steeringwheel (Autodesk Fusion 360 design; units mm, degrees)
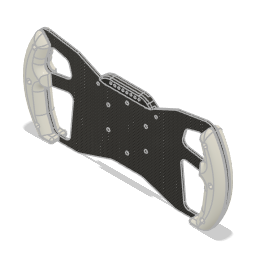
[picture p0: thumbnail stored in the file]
base_mesh_feature "Base Mesh Feature1"
base_mesh_feature "Base Mesh Feature2"
sketch "Sketch1" plane through (0, 0, 0) normal (0, 0, 1) x axis (1, 0, 0)
  line L1 (0, 45.0119) -> (-36.4037, 45.0119)
  line L2 (0, -55.8322) -> (-23.9037, -55.8322)
  line L3 (-78.4037, -74.0428) -> (-135.2692, -74.0428)
  line L4 (-78.4037, -74.0428) -> (-23.9037, -55.8322)
  line L5 (-36.4037, 45.0119) -> (-80, 65)
  line L6 (-80, 65) -> (-130.4747, 80.2858)
  line L7 (0, -94.3953) -> (0, 64.7225)
  line L8 (-162, -94.9093) -> (-162, 34.6125)
  line L9 (-87.3968, 22.1611) -> (-94.5571, 46.7526)
  line L10 (-133.0987, 14.2514) -> (-87.3968, 22.1611)
  line L11 (-129.3037, 34.2572) -> (-133.0987, 14.2514)
  line L12 (-122.9012, 54.3594) -> (-129.3037, 34.2572)
  line L13 (-94.5571, 46.7526) -> (-122.9012, 54.3594)
  line L14 (-85.8742, 4.1597) -> (-132.1872, -3.9752)
  line L15 (-92.2344, -65.3438) -> (-85.8742, 4.1597)
  line L16 (-117.9107, -65.3438) -> (-92.2344, -65.3438)
  line L17 (-127.1032, -41.9612) -> (-117.9107, -65.3438)
  line L18 (-132.1872, -3.9752) -> (-127.1032, -41.9612)
  line L19 (0, -55.8322) -> (0, 45.0119)
  line L20 (-137.7533, 71.7066) -> (-122.9012, 54.3594)
  line L21 (-135.2692, -74.0428) -> (-117.9107, -65.3438)
  line L22 (-121.746, -2.1412) -> (-123.3157, 15.9445)
  line L23 (-133.3138, 50.7008) -> (-134.7148, 46.7871)
  line L24 (-136.0027, 53.871) -> (-133.3138, 50.7008)
  line L25 (-140.0926, 53.1274) -> (-136.0027, 53.871)
  line L26 (-141.4936, 49.2136) -> (-140.0926, 53.1274)
  line L27 (-138.8046, 46.0435) -> (-141.4936, 49.2136)
  line L28 (-134.7148, 46.7871) -> (-138.8046, 46.0435)
  line L29 (-129.2785, -57.5552) -> (-131.7848, -60.8715)
  line L30 (-130.8973, -53.7264) -> (-129.2785, -57.5552)
  line L31 (-135.0226, -53.214) -> (-130.8973, -53.7264)
  line L32 (-137.5289, -56.5304) -> (-135.0226, -53.214)
  line L33 (-135.91, -60.3591) -> (-137.5289, -56.5304)
  line L34 (-131.7848, -60.8715) -> (-135.91, -60.3591)
  line L35 (-143.0554, 0.1029) -> (-142.9773, -4.0533)
  line L36 (-146.6938, 2.1134) -> (-143.0554, 0.1029)
  line L37 (-150.2541, -0.0323) -> (-146.6938, 2.1134)
  line L38 (-150.176, -4.1885) -> (-150.2541, -0.0323)
  line L39 (-146.5376, -6.199) -> (-150.176, -4.1885)
  line L40 (-142.9773, -4.0533) -> (-146.5376, -6.199)
  line L41 (-110.0525, -74.0428) -> (-110.0525, -65.3438)
  line L42 (-140.0719, -67.8017) -> (-120.4577, -58.8651)
  line L43 (-80, 65) -> (-135.8386, 74.1301)
  circle C1 centre (0, 35.0082) radius 2.5
  circle C2 centre (30.215, 17.6651) radius 2.5
  circle C3 centre (-30.371, 17.3955) radius 2.5
  circle C4 centre (-30.3591, -17.4163) radius 2.5
  circle C5 centre (0, -34.9879) radius 2.5
  circle C6 centre (30.2515, -17.6025) radius 2.5
  arc A1 centre (-45, 0.3916) radius 117 clockwise from (-135.2692, -74.0428) to (-130.4747, 80.2858)
  circle C7 centre (0, 0) radius 35
  circle C8 centre (-133.4037, -57.0428) radius 2.1
  circle C9 centre (-146.6157, -2.0428) radius 2.1
  circle C10 centre (-137.4037, 49.9572) radius 2.1
  circle C11 centre (-146.6157, -2.0428) radius 3.75
  circle C12 centre (-137.4037, 49.9572) radius 3.75
  circle C13 centre (-133.4037, -57.0428) radius 3.75
  point P6 (0, -34.9879)
  point P9 (0, 45.0119)
  point P11 (0, -55.8322)
  point P25 (-122.9012, 54.3594)
  point P23 (-133.0987, 14.2514)
  point P26 (-85.8742, 4.1597)
  point P2 (0, 35.0082)
  point P31 (0, 0)
  point P3 (30.215, 17.6651)
  point P7 (30.2515, -17.6025)
  point P5 (-30.3591, -17.4163)
  point P4 (-30.371, 17.3955)
  point P32 (-137.7533, 71.7066)
  point P33 (-123.3157, 15.9445)
  point P34 (-121.746, -2.1412)
  point P36 (-146.6157, -2.0428)
  point P38 (-146.6157, -2.0428)
  point P37 (-137.4037, 49.9572)
  point P45 (-137.4037, 49.9572)
  point P35 (-133.4037, -57.0428)
  point P52 (-133.4037, -57.0428)
  point P59 (-146.6157, -2.0428)
  point P60 (-146.6157, -2.0428)
  point P61 (-137.4037, 49.9572)
  point P62 (-133.4037, -57.0428)
  point P63 (-110.0525, -65.3438)
  point P64 (-110.0525, -74.0428)
  point P65 (-120.4577, -58.8651)
  point P66 (-140.0719, -67.8017)
  point P1 (0, 0)
  point P67 (-135.8386, 74.1301)
  horizontal L1
  parallel L1 L2
  horizontal L3
  perpendicular L2 L7
  coincident P6 L7
  coincident P9 L7
  coincident P11 L7
  vertical L8
  tangent A1 L8
  coincident P25 L13
  coincident L10 P23
  horizontal L16
  coincident L14 P26
  coincident P2 L7
  coincident L19 P31
  coincident P3 C7
  coincident P7 C7
  coincident P5 C7
  coincident P4 C7
  coincident A1 P32
  coincident L10 P33
  coincident L14 P34
  coincident P36 P38
  coincident P37 P45
  coincident P35 P52
  coincident P38 P59
  coincident P59 P60
  coincident P45 P61
  coincident P52 P62
  coincident L16 P63
  perpendicular L16 L41
  coincident L3 P64
  coincident L17 P65
  coincident A1 P66
  coincident P1 P31
  coincident A1 P67
  dimension "d1" diameter C1 = 5
  dimension "d2" diameter C2 = 5 (= "d1")
  dimension "d3" diameter C6 = 5 (= "d1")
  dimension "d4" diameter C5 = 5 (= "d1")
  dimension "d5" diameter C4 = 5 (= "d1")
  dimension "d6" diameter C3 = 5 (= "d1")
  dimension "d7" radius A1 = 117
  dimension "d9" distance L7 L8 = 162
  dimension "d21" diameter C7 = 70
  dimension "d37" diameter C8 = 4.2 (= "d39")
  dimension "d38" diameter C9 = 4.2 (= "d39")
  dimension "d39" diameter C10 = 4.2
  dimension "d41" distance P45 L28 = 3.6
  dimension "d42" distance P52 L34 = 3.6 (= "d41")
  dimension "d43" distance P59 L40 = 3.6 (= "d41")
  dimension "d44" diameter C11 = 7.5 (= "d45")
  dimension "d45" diameter C12 = 7.5
  dimension "d46" diameter C13 = 7.5 (= "d45")
extrude "Extrude1" new body sketch "Sketch1" profile of C1 C3 C4 C5 L1 L2 L3 L4 L5 A1 L9 L10 L11 L12 L13 L14 L15 L16 L17 L18 L19 C7 L20 L21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 along normal blind 3 bodies "BasePlate"
fillet "Fillet1" radius 8
fillet "Fillet2" radius 20
fillet "Fillet3" radius 8
modify "Modify2"
extrude "Extrude2" new body sketch "Sketch1" profile of A1 L10 L11 L12 L14 L17 L18 L20 L21 L22 along normal blind 15 and along normal blind 3 bodies "FrontGrip1"
extrude "Extrude3" new body sketch "Sketch1" profile of A1 L10 L11 L12 L14 L17 L18 L20 L21 L22 against normal blind 12 bodies "RearGrip1"
fillet "Fillet5" radius 8
fillet "Fillet6" radius 5
chamfer "Chamfer1" distance 7
fillet "Fillet7" radius 10
extrude "Extrude4" cut sketch "Sketch1" profile of C8 C9 C10 L23 L24 L25 L26 L27 L28 L29 L30 L31 L32 L33 L34 L35 L36 L37 L38 L39 L40 C11 C12 C13 along normal blind 25 and along normal blind 9
extrude "Extrude5" cut sketch "Sketch1" profile of C8 C9 C10 L37 along normal blind 25
extrude "Extrude6" cut sketch "Sketch1" profile of C8 C9 C10 C11 C12 C13 against normal blind 30 and against normal blind 6
extrude "Extrude7" cut sketch "Sketch1" profile of C8 C9 C10 L37 against normal blind 22
extrude "Extrude8" add sketch "Sketch1" profile of L3 A1 L16 L17 L21 L41 L42 against normal blind 12
extrude "Extrude9" add sketch "Sketch1" profile of L3 A1 L16 L17 L21 L41 L42 along normal blind 15 and along normal blind 3
fillet "Fillet9" radius 3
fillet "Fillet10" radius 10
fillet "Fillet11" radius 4
mirror "Mirror1" mirrorStitchTolerance 0.1
mirror "Mirror2" mirrorStitchTolerance 0.1 bodies "FrontGrip1 (1)", "RearGrip1 (1)"
fillet "Fillet12" radius 16
sketch "Sketch2" plane through (0, 0, 0) normal (0, 0, 1) x axis (1, 0, 0)
  line L1 (26.75, 57.2119) -> (-26.75, 57.2119)
  line L2 (26.75, 47.0119) -> (26.75, 57.2119)
  line L3 (-26.75, 47.0119) -> (26.75, 47.0119)
  line L4 (-26.75, 57.2119) -> (-26.75, 47.0119)
  line L5 (0, -49.4794) -> (0, 57.2119)
  line L6 (-20.25, 55.9119) -> (-25.75, 55.9119)
  line L7 (-20.25, 50.4119) -> (-20.25, 55.9119)
  line L8 (-25.75, 50.4119) -> (-20.25, 50.4119)
  line L9 (-25.75, 55.9119) -> (-25.75, 50.4119)
  line L10 (-13.75, 55.9119) -> (-19.25, 55.9119)
  line L11 (-13.75, 50.4119) -> (-13.75, 55.9119)
  line L12 (-19.25, 50.4119) -> (-13.75, 50.4119)
  line L13 (-19.25, 55.9119) -> (-19.25, 50.4119)
  line L14 (-7.25, 55.9119) -> (-12.75, 55.9119)
  line L15 (-7.25, 50.4119) -> (-7.25, 55.9119)
  line L16 (-12.75, 50.4119) -> (-7.25, 50.4119)
  line L17 (-12.75, 55.9119) -> (-12.75, 50.4119)
  line L18 (-0.75, 55.9119) -> (-6.25, 55.9119)
  line L19 (-0.75, 50.4119) -> (-0.75, 55.9119)
  line L20 (-6.25, 50.4119) -> (-0.75, 50.4119)
  line L21 (-6.25, 55.9119) -> (-6.25, 50.4119)
  line L22 (5.75, 55.9119) -> (0.25, 55.9119)
  line L23 (5.75, 50.4119) -> (5.75, 55.9119)
  line L24 (0.25, 50.4119) -> (5.75, 50.4119)
  line L25 (0.25, 55.9119) -> (0.25, 50.4119)
  line L26 (12.25, 55.9119) -> (6.75, 55.9119)
  line L27 (12.25, 50.4119) -> (12.25, 55.9119)
  line L28 (6.75, 50.4119) -> (12.25, 50.4119)
  line L29 (6.75, 55.9119) -> (6.75, 50.4119)
  line L30 (18.75, 55.9119) -> (13.25, 55.9119)
  line L31 (18.75, 50.4119) -> (18.75, 55.9119)
  line L32 (13.25, 50.4119) -> (18.75, 50.4119)
  line L33 (13.25, 55.9119) -> (13.25, 50.4119)
  line L34 (25.25, 55.9119) -> (19.75, 55.9119)
  line L35 (25.25, 50.4119) -> (25.25, 55.9119)
  line L36 (19.75, 50.4119) -> (25.25, 50.4119)
  line L37 (19.75, 55.9119) -> (19.75, 50.4119)
  line L38 (31.75, 59.5119) -> (-31.25, 59.5119)
  line L39 (31.75, 45.0119) -> (31.75, 59.5119)
  line L40 (-31.25, 45.0119) -> (31.75, 45.0119)
  line L41 (-31.25, 59.5119) -> (-31.25, 45.0119)
  line L42 (32.0374, 45.0119) -> (-32.0374, 45.0119)
  line L43 (0, -94.3953) -> (0, 64.7225)
  line L44 (-50.4011, 43.4422) -> (-31.25, 59.5119)
  line L45 (-42.43, 34.4789) -> (-31.25, 45.0119)
  line L46 (47.0444, 38.846) -> (-46.5444, 38.846)
  line L47 (50.9011, 43.4422) -> (31.75, 59.5119)
  line L48 (42.93, 34.4789) -> (31.75, 45.0119)
  line L49 (25.25, 53.1619) -> (-25.75, 53.1619)
  line L50 (-23, 50.4119) -> (-23, 55.9119)
  line L51 (-16.5, 50.4119) -> (-16.5, 55.9119)
  line L52 (-10, 50.4119) -> (-10, 55.9119)
  line L53 (-3.5, 50.4119) -> (-3.5, 55.9119)
  line L54 (3, 50.4119) -> (3, 55.9119)
  line L55 (9.5, 50.4119) -> (9.5, 55.9119)
  line L56 (16, 50.4119) -> (16, 55.9119)
  line L57 (22.5, 50.4119) -> (22.5, 55.9119)
  line L58 (23.75, 49.5119) -> (26.75, 49.5119)
  line L59 (23.75, 45.0119) -> (23.75, 49.5119)
  line L60 (26.75, 45.0119) -> (23.75, 45.0119)
  line L61 (26.75, 49.5119) -> (26.75, 45.0119)
  line L62 (-19.75, 49.5119) -> (-26.75, 49.5119)
  line L63 (-19.75, 45.0119) -> (-19.75, 49.5119)
  line L64 (-25.9, 49.5119) -> (-26.75, 49.5119)
  line L65 (-26.75, 45.0119) -> (-26.75, 47.0119)
  line L66 (-19.75, 56.5) -> (-26.75, 56.5)
  line L67 (-19.75, 49.5119) -> (-19.75, 56.5)
  circle C1 centre (-46.5444, 38.846) radius 6
  circle C2 centre (47.0444, 38.846) radius 6
  circle C3 centre (-46.5444, 38.846) radius 2.1
  circle C4 centre (47.0444, 38.846) radius 2.1
  circle C5 centre (-23, 53.1619) radius 1.75
  circle C6 centre (-16.5, 53.1619) radius 1.75
  circle C7 centre (-10, 53.1619) radius 1.75
  circle C8 centre (-3.5, 53.1619) radius 1.75
  circle C9 centre (3, 53.1619) radius 1.75
  circle C10 centre (9.5, 53.1619) radius 1.75
  circle C11 centre (16, 53.1619) radius 1.75
  circle C12 centre (22.5, 53.1619) radius 1.75
  circle C13 centre (31.25, 51.0119) radius 1.1
  circle C14 centre (-31.25, 51.0119) radius 1.1
  circle C15 centre (31.25, 51.0119) radius 4.5
  circle C16 centre (-31.25, 51.0119) radius 4.5
  point P6 (0, 57.2119)
  point P49 (-50.4011, 43.4422)
  point P50 (-42.43, 34.4789)
  point P48 (-46.5444, 38.846)
  point P51 (-46.5444, 38.846)
  point P52 (47.0444, 38.846)
  point P53 (47.0444, 38.846)
  point P54 (50.9011, 43.4422)
  point P55 (42.93, 34.4789)
  point P59 (-25.75, 53.1619)
  point P60 (25.25, 53.1619)
  point P58 (-23, 53.1619)
  point P61 (-23, 55.9119)
  point P62 (-23, 50.4119)
  point P63 (-16.5, 55.9119)
  point P64 (-16.5, 50.4119)
  point P65 (-10, 55.9119)
  point P66 (-10, 50.4119)
  point P67 (-3.5, 55.9119)
  point P68 (-3.5, 50.4119)
  point P69 (3, 55.9119)
  point P70 (3, 50.4119)
  point P71 (9.5, 55.9119)
  point P72 (9.5, 50.4119)
  point P73 (16, 55.9119)
  point P74 (16, 50.4119)
  point P75 (22.5, 55.9119)
  point P76 (22.5, 50.4119)
  point P77 (-16.5, 53.1619)
  point P78 (-10, 53.1619)
  point P79 (-3.5, 53.1619)
  point P80 (3, 53.1619)
  point P81 (9.5, 53.1619)
  point P82 (16, 53.1619)
  point P83 (22.5, 53.1619)
  point P86 (26.75, 49.5119)
  point P92 (-26.75, 49.5119)
  point P94 (-19.75, 45.0119)
  point P95 (-26.75, 45.0119)
  point P96 (-26.75, 56.5)
  point P2 (-26.75, 57.2119)
  point P3 (26.75, 57.2119)
  point P5 (-26.75, 47.0119)
  point P8 (-25.75, 55.9119)
  point P9 (-20.25, 55.9119)
  point P11 (-25.75, 50.4119)
  point P12 (-19.25, 55.9119)
  point P13 (-13.75, 55.9119)
  point P15 (-19.25, 50.4119)
  point P16 (-12.75, 55.9119)
  point P17 (-7.25, 55.9119)
  point P19 (-12.75, 50.4119)
  point P20 (-6.25, 55.9119)
  point P21 (-0.75, 55.9119)
  point P23 (-6.25, 50.4119)
  point P24 (0.25, 55.9119)
  point P25 (5.75, 55.9119)
  point P28 (6.75, 55.9119)
  point P29 (12.25, 55.9119)
  point P32 (13.25, 55.9119)
  point P33 (18.75, 55.9119)
  point P36 (19.75, 55.9119)
  point P37 (25.25, 55.9119)
  point P31 (6.75, 50.4119)
  point P35 (13.25, 50.4119)
  point P39 (19.75, 50.4119)
  point P41 (31.75, 59.5119)
  point P42 (31.75, 45.0119)
  point P40 (-31.25, 59.5119)
  point P84 (31.25, 51.0119)
  point P85 (-31.25, 51.0119)
  point P87 (23.75, 49.5119)
  point P88 (23.75, 45.0119)
  point P93 (-19.75, 49.5119)
  horizontal L1
  vertical L2
  horizontal L3
  vertical L4
  midpoint L1 P6
  perpendicular L3 L5
  horizontal L6
  vertical L7
  horizontal L8
  vertical L9
  horizontal L10
  vertical L11
  horizontal L12
  vertical L13
  horizontal L14
  vertical L15
  horizontal L16
  vertical L17
  horizontal L18
  vertical L19
  horizontal L20
  vertical L21
  horizontal L22
  vertical L23
  horizontal L24
  vertical L25
  horizontal L26
  vertical L27
  horizontal L28
  vertical L29
  horizontal L30
  vertical L31
  horizontal L32
  vertical L33
  horizontal L34
  vertical L35
  horizontal L36
  vertical L37
  horizontal L38
  vertical L39
  horizontal L40
  vertical L41
  collinear L40 L42
  collinear L5 L43
  coincident C1 P49
  tangent C1 L44
  coincident C1 P50
  tangent C1 L45
  coincident P48 P51
  perpendicular L43 L46
  coincident P52 P53
  coincident C2 P54
  tangent C2 L47
  coincident C2 P55
  tangent C2 L48
  concentric C1 C3
  concentric C2 C4
  midpoint L9 P59
  midpoint L35 P60
  coincident P58 L49
  midpoint L6 P61
  midpoint L8 P62
  midpoint L10 P63
  midpoint L12 P64
  midpoint L14 P65
  midpoint L16 P66
  midpoint L18 P67
  midpoint L20 P68
  midpoint L22 P69
  midpoint L24 P70
  midpoint L26 P71
  midpoint L28 P72
  midpoint L30 P73
  midpoint L32 P74
  midpoint L34 P75
  midpoint L36 P76
  midpoint P58 L50
  midpoint L51 P77
  midpoint L52 P78
  midpoint L53 P79
  midpoint L54 P80
  midpoint L55 P81
  midpoint L56 P82
  midpoint L57 P83
  horizontal L58
  vertical L59
  horizontal L60
  vertical L61
  coincident L2 P86
  collinear L40 L60
  concentric C13 C15
  concentric C14 C16
  coincident L4 P92
  perpendicular L4 L62
  vertical L63
  coincident L40 P94
  coincident L42 P94
  perpendicular L4 L64
  coincident L42 P95
  vertical L65
  perpendicular L62 L67
  coincident L4 P96
  perpendicular L4 L66
  dimension "d78" distance P2 P3 = 53.5
  dimension "d79" distance P2 P5 = 10.2
  dimension "d80" distance P8 P9 = 5.5
  dimension "d81" distance P8 P11 = 5.5
  dimension "d82" distance P12 P13 = 5.5 (= "d80")
  dimension "d83" distance P12 P15 = 5.5 (= "d81")
  dimension "d84" distance P16 P17 = 5.5 (= "d80")
  dimension "d85" distance P16 P19 = 5.5 (= "d81")
  dimension "d86" distance P20 P21 = 5.5 (= "d80")
  dimension "d87" distance P20 P23 = 5.5 (= "d81")
  dimension "d88" distance P24 P25 = 5.5 (= "d80")
  dimension "d89" distance P28 P29 = 5.5 (= "d80")
  dimension "d90" distance P32 P33 = 5.5 (= "d80")
  dimension "d91" distance P36 P37 = 5.5 (= "d80")
  dimension "d92" distance L22 L24 = 5.5 (= "d80")
  dimension "d93" distance P28 P31 = 5.5 (= "d80")
  dimension "d94" distance P32 P35 = 5.5 (= "d80")
  dimension "d95" distance P36 P39 = 5.5 (= "d80")
  dimension "d96" distance L7 L13 = 1
  dimension "d97" distance L11 L17 = 1 (= "d96")
  dimension "d98" distance L15 L21 = 1 (= "d96")
  dimension "d99" distance L19 L25 = 1 (= "d96")
  dimension "d100" distance L23 L29 = 1 (= "d96")
  dimension "d101" distance L27 L33 = 1 (= "d96")
  dimension "d102" distance L31 L37 = 1 (= "d96")
  dimension "d103" distance L1 L6 = 1.3
  dimension "d104" distance L1 L10 = 1.3 (= "d103")
  dimension "d105" distance L1 L14 = 1.3 (= "d103")
  dimension "d106" distance L1 L18 = 1.3 (= "d103")
  dimension "d107" distance L1 L22 = 1.3 (= "d103")
  dimension "d108" distance L1 L26 = 1.3 (= "d103")
  dimension "d109" distance L1 L30 = 1.3 (= "d103")
  dimension "d110" distance L1 L34 = 1.3 (= "d103")
  dimension "d112" distance P41 P42 = 14.5
  dimension "d113" distance P40 P41 = 63
  dimension "d114" distance L2 L39 = 5
  dimension "d115" distance L4 L9 = 1
  dimension "d116" distance L3 L40 = 2
  dimension "d117" diameter C1 = 12
  dimension "d118" diameter C2 = 12 (= "d117")
  dimension "d119" angle L39 L47 = 50 (= "d120")
  dimension "d120" angle L41 L44 = 50
  dimension "d121" distance P40 P49 = 25
  dimension "d122" diameter C3 = 4.2
  dimension "d123" diameter C4 = 4.2
  dimension "d126" diameter C5 = 3.5
  dimension "d127" diameter C12 = 3.5 (= "d126")
  dimension "d128" diameter C11 = 3.5 (= "d126")
  dimension "d129" diameter C10 = 3.5 (= "d126")
  dimension "d130" diameter C9 = 3.5 (= "d126")
  dimension "d131" diameter C8 = 3.5 (= "d126")
  dimension "d132" diameter C7 = 3.5 (= "d126")
  dimension "d133" diameter C6 = 3.5 (= "d126")
  dimension "d152" diameter C13 = 2.2 (= "d153")
  dimension "d153" diameter C14 = 2.2
  dimension "d154" distance L2 P84 = 4.5
  dimension "d155" distance L4 P85 = 4.5 (= "d154")
  dimension "d156" distance L38 P84 = 8.5
  dimension "d157" distance L38 P85 = 8.5 (= "d156")
  dimension "d173" distance P86 P87 = 3
  dimension "d174" distance P87 P88 = 4.5
  dimension "d181" diameter C15 = 9
  dimension "d182" diameter C16 = 9 (= "d181")
  dimension "d189" distance P93 P94 = 4.5
  dimension "d190" distance P92 P93 = 7
extrude "Extrude10" new body sketch "Sketch2" profile of L39 L41 C1 L44 L45 C2 L47 L48 C3 C4 C15 C16 against normal blind 3 bodies "LEDBody"
extrude "Extrude11" add sketch "Sketch2" profile of L1 L2 L3 L4 L6 L7 L8 L9 L10 L11 L12 L13 L14 L15 L16 L17 L18 L19 L20 L21 L22 L23 L24 L25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 along normal blind 7
extrude "Extrude12" cut of existing geometry blind -3 second side blind -9
fillet "Fillet13" radius 22
extrude "Extrude13" cut sketch "Sketch2" profile of C5 C6 C7 C8 C9 C10 C11 C12 along normal blind 10
extrude "Extrude14" cut sketch "Sketch2" profile of L1 L2 L3 L4 L6 L7 L8 L9 L10 L11 L12 L13 L14 L15 L16 L17 L18 L19 L20 L21 L22 L23 L24 L25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 along normal blind 4.5 and against normal blind 5
extrude "Extrude15" cut sketch "Sketch2" profile of C3 C4 along normal blind 20
extrude "Extrude17" new body of existing geometry blind 3 bodies "LEDCover"
extrude "Extrude18" add sketch "Sketch2" profile of L1 L2 L3 L4 L6 L7 L8 L9 L10 L11 L12 L13 L14 L15 L16 L17 L18 L19 L20 L21 L22 L23 L24 L25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 against normal blind 3
extrude "Extrude19" cut sketch "Sketch2" profile of C13 C14 along normal blind 5 and against normal blind 15
chamfer "Chamfer3" distance 1.5
move_face "MoveFace1"
move_face "MoveFace2"
move_face "MoveFace3"
move_face "MoveFace4"
fillet "Fillet14" radius 2.5
extrude "Extrude22" cut sketch "Sketch2" profile of L3 L4 L40 L42 C16 L62 L63 L64 L65 against normal blind 3
extrude "Extrude25" cut sketch "Sketch2" profile of L4 L6 L8 L9 C5 L62 L64 L66 L67 against normal blind 1.5
fillet "Fillet15" radius 1
offset_faces "OffsetFaces1" distance -0.4
offset_faces "OffsetFaces2" distance -0.2
fillet "Fillet16" radius 2
chamfer "Chamfer4" distance 1.5
chamfer "Chamfer5" distance 2
extrude "Extrude23" new body sketch "Sketch2" profile of L1 L2 L3 L4 L6 L7 L8 L9 L10 L11 L12 L13 L14 L15 L16 L17 L18 L19 L20 L21 L22 L23 L24 L25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 along normal blind 1 bodies "Circuit"
extrude "Extrude24" add sketch "Sketch2" profile of C5 C6 C7 C8 C9 C10 C11 C12 along normal blind 3
fillet "Fillet17" radius 2
extrude "Extrude26" cut of existing geometry blind -0.1
sketch "Sketch3" plane through (0, 0, 0) normal (0, 0, 1) x axis (1, 0, 0)
  line L1 (-18.25, 56.5) -> (-28.25, 56.5)
  line L2 (-18.25, 45.0119) -> (-18.25, 56.5)
  line L3 (31.55, 45.0119) -> (-18.25, 45.0119)
  line L4 (31.55, 46.5398) -> (31.55, 45.0119)
  line L5 (31.55, 58.08) -> (31.55, 55.4841)
  line L6 (-23.2427, 59.5119) -> (23.7427, 59.5119)
  line L7 (-31.05, 55.5119) -> (-31.05, 58.08)
  line L8 (-31.05, 45.0119) -> (-31.05, 46.5119)
  line L9 (-28.25, 45.0119) -> (-31.05, 45.0119)
  line L10 (-28.25, 56.5) -> (-28.25, 45.0119)
  line L11 (-4.65, 52.0119) -> (-13.25, 52.0119)
  line L12 (-4.65, 48.0119) -> (-4.65, 52.0119)
  line L13 (-13.25, 48.0119) -> (-4.65, 48.0119)
  line L14 (-13.25, 52.0119) -> (-13.25, 48.0119)
  line L15 (-6.45, 52.0119) -> (-11.45, 52.0119)
  line L16 (-6.45, 48.0119) -> (-6.45, 52.0119)
  line L17 (-11.45, 48.0119) -> (-6.45, 48.0119)
  line L18 (-11.45, 52.0119) -> (-11.45, 48.0119)
  arc A1 centre (31.05, 51.0119) radius 4.5 clockwise from (31.55, 55.4841) to (31.55, 46.5398)
  arc A2 centre (23.7427, 37.5119) radius 22 clockwise from (23.7427, 59.5119) to (31.55, 58.08)
  arc A3 centre (-23.2427, 37.5119) radius 22 clockwise from (-31.05, 58.08) to (-23.2427, 59.5119)
  arc A4 centre (-31.05, 51.0119) radius 4.5 clockwise from (-31.05, 46.5119) to (-31.05, 55.5119)
  circle C1 centre (-31.25, 51.0119) radius 1.1
  circle C2 centre (31.25, 51.0119) radius 1.1
  point P28 (-6.45, 48.0119)
  point P26 (-11.45, 52.0119)
  point P22 (-13.25, 52.0119)
  point P25 (-13.25, 48.0119)
  horizontal L11
  vertical L12
  horizontal L13
  vertical L14
  horizontal L15
  vertical L16
  horizontal L17
  vertical L18
  coincident L13 P28
  coincident L11 P26
  dimension "d202" distance L3 L17 = 3
  dimension "d203" distance P22 P25 = 4
  dimension "d204" distance L14 L18 = 1.8
  dimension "d205" distance L12 L16 = 1.8
  dimension "d206" distance L16 L18 = 5
  dimension "d207" distance L2 L14 = 5
extrude "Extrude27" cut sketch "Sketch3" profile of L11 L12 L13 L14 L16 L18 against normal blind 10
extrude "Extrude28" cut sketch "Sketch3" profile of L11 L13 L15 L16 L17 L18 against normal blind 1.6
fillet "Fillet18" radius 0.5
component_from_bodies "Body->Comp1"
component_from_bodies "Body->Comp2"
component_from_bodies "Body->Comp3"
component_from_bodies "Body->Comp4"
component_from_bodies "Body->Comp5"
component_from_bodies "Body->Comp6"
component_from_bodies "Body->Comp7"
step "Body->Comp1"
step "Body->Comp2"
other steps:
create_component "CreateComponent1"
base_feature "Base Feature1" bodies "BasePlate"
remove_body "RemoveBody1"
create_component "CreateComponent2"
base_feature "Base Feature1" bodies "FrontGrip1"
remove_body "RemoveBody2"
create_component "CreateComponent3"
base_feature "Base Feature1" bodies "RearGrip1"
remove_body "RemoveBody3"
create_component "CreateComponent4"
base_feature "Base Feature1" bodies "FrontGrip1 (1)"
remove_body "RemoveBody4"
create_component "CreateComponent5"
base_feature "Base Feature1" bodies "RearGrip1 (1)"
remove_body "RemoveBody5"
create_component "CreateComponent6"
base_feature "Base Feature1" bodies "LEDBody"
remove_body "RemoveBody6"
create_component "CreateComponent7"
base_feature "Base Feature1" bodies "LEDCover"
remove_body "RemoveBody7"
create_component "CreateComponent8"
copy_paste_meshes "CutPasteMeshes1"
create_component "CreateComponent9"
copy_paste_meshes "CutPasteMeshes1"
named bodies: "BasePlate", "FrontGrip1", "RearGrip1", "FrontGrip1 (1)", "RearGrip1 (1)", "LEDBody", "LEDCover", "Circuit"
